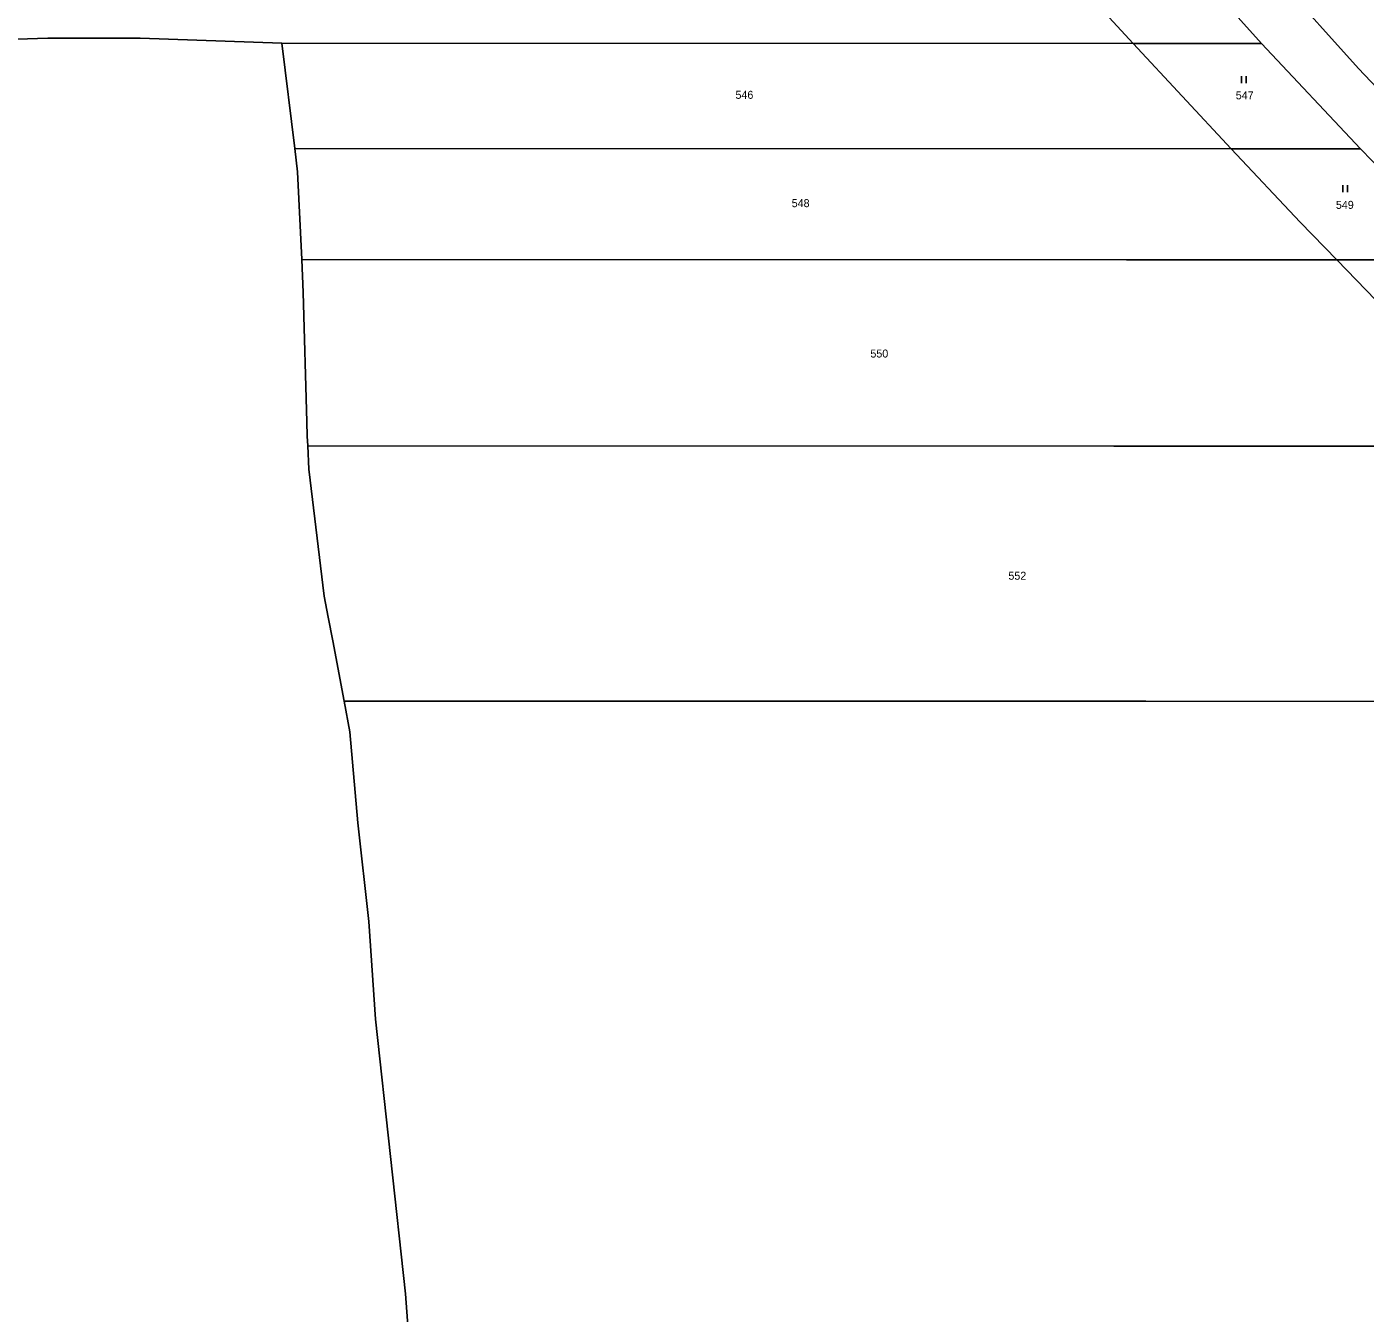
# Model space of a CAD drawing. Extents: x -769392 to -767038, y -1018329 to -1015269.
# Drawn here: x -768709.3 to -768424.9, y -1018061.3 to -1017788.1 of the extents above; entities that cross this region are included whole.
import ezdxf

# ---------------------------------------------------------------- set-up
doc = ezdxf.new("R2010")
doc.units = 0
doc.header["$LTSCALE"] = 0.68
doc.layers.add('1', color=7, linetype='Continuous', lineweight=25)
doc.layers.add('3', color=7, linetype='Continuous', lineweight=25)
doc.layers.add('2', color=7, linetype='Continuous')

msp = doc.modelspace()

# ---------------------------------------------------------------- linework, layer by layer
at = {"layer": '1'}
for p, q in [((-768704.84, -1017790.52), (-768744.51, -1017791.83)), ((-768685.24, -1017790.52), (-768704.84, -1017790.52)), ((-768655.09, -1017791.57), (-768685.24, -1017790.52)), ((-768655.09, -1017791.57), (-768474.24, -1017791.62)), ((-768652.37, -1017813.96), (-768655.09, -1017791.57)), ((-768474.24, -1017791.62), (-768446.96, -1017791.63)), ((-768474.24, -1017791.62), (-768453.43, -1017814.02)), ((-768446.96, -1017791.63), (-768425.91, -1017814.03)), ((-768651.77, -1017818.93), (-768652.37, -1017813.96)), ((-768652.37, -1017813.96), (-768453.43, -1017814.02)), ((-768453.43, -1017814.02), (-768425.91, -1017814.03)), ((-768425.91, -1017814.03), (-768403.04, -1017837.62)), ((-768650.89, -1017837.54), (-768651.77, -1017818.93)), ((-768650.56, -1017844.5), (-768650.89, -1017837.54)), ((-768430.93, -1017837.61), (-768403.04, -1017837.62)), ((-768649.79, -1017872.03), (-768650.56, -1017844.5)), ((-768649.79, -1017872.03), (-768649.71, -1017875.04)), ((-768649.62, -1017877.09), (-768649.71, -1017875.04)), ((-768649.41, -1017882.04), (-768649.62, -1017877.09)), ((-768646.09, -1017909), (-768649.41, -1017882.04)), ((-768646.09, -1017909), (-768645.24, -1017913.51)), ((-768645.24, -1017913.51), (-768644.29, -1017918.54)), ((-768641.88, -1017931.31), (-768644.29, -1017918.54)), ((-768640.64, -1017937.87), (-768641.88, -1017931.31)), ((-768638.95, -1017957.17), (-768640.64, -1017937.87)), ((-768636.61, -1017978.12), (-768638.95, -1017957.17)), ((-768635.19, -1017998.86), (-768636.61, -1017978.12)), ((-768628.82, -1018057.21), (-768635.19, -1017998.86)), ((-768625.55, -1018100.63), (-768628.82, -1018057.21))]:
    msp.add_line(p, q, dxfattribs=at)
for points in [[(-768705.98, -1017641.65), (-768706.39, -1017662.94), (-768639.27, -1017687.75), (-768573.5, -1017714.57), (-768551.54, -1017722.94), (-768539.78, -1017729.34), (-768531.65, -1017734.9), (-768503.15, -1017760.26), (-768474.24, -1017791.62)], [(-768705.98, -1017641.65), (-768677.55, -1017652.28), (-768632.03, -1017669.11), (-768566.16, -1017695.96), (-768543.16, -1017704.73), (-768529.32, -1017712.26), (-768519.3, -1017719.12), (-768506.34, -1017730.87), (-768489.12, -1017745.98), (-768477.69, -1017757.38), (-768446.96, -1017791.63)], [(-768556.34, -1017687.33), (-768551.42, -1017689.19), (-768536.34, -1017696.77), (-768524.28, -1017703.42), (-768512.59, -1017711.44), (-768499.71, -1017721.64), (-768477.3, -1017741.63), (-768460.5, -1017758.91), (-768426.34, -1017796.93), (-768411.6, -1017812.49), (-768402.15, -1017820.51), (-768391.72, -1017831.23), (-768374.38, -1017847.47), (-768326.06, -1017889.73), (-768309.54, -1017904.05), (-768295.37, -1017917.29), (-768244.47, -1017965.89)], [(-768430.93, -1017837.61), (-768438.74, -1017829.57), (-768453.43, -1017814.02)], [(-768650.89, -1017837.54), (-768475.66, -1017837.6), (-768430.93, -1017837.61)], [(-768388.38, -1017877.17), (-768400.15, -1017867.09), (-768416.47, -1017852.5), (-768430.93, -1017837.61)], [(-768649.62, -1017877.09), (-768478.31, -1017877.14), (-768388.38, -1017877.17)], [(-768641.88, -1017931.31), (-768471.54, -1017931.37), (-768324.96, -1017931.42)]]:
    msp.add_lwpolyline(points, dxfattribs=at)
at = {"layer": '3'}
for p, q in [((-768451.191, -1017800.08), (-768451.191, -1017798.58)), ((-768450.19, -1017800.08), (-768450.19, -1017798.58)), ((-768429.671, -1017823.25), (-768429.671, -1017821.75)), ((-768428.67, -1017823.25), (-768428.67, -1017821.75))]:
    msp.add_line(p, q, dxfattribs=at)

# ---------------------------------------------------------------- texts
at = {"layer": '2'}
for s, p in [('546', (-768558.72, -1017803.395)), ('547', (-768452.42, -1017803.495)), ('548', (-768546.77, -1017826.405)), ('549', (-768431.14, -1017826.765)), ('550', (-768530.05, -1017858.345)), ('552', (-768500.73, -1017905.545))]:
    msp.add_text(s, height=1.7, dxfattribs=at).set_placement(p)

doc.saveas('drawing.dxf')
